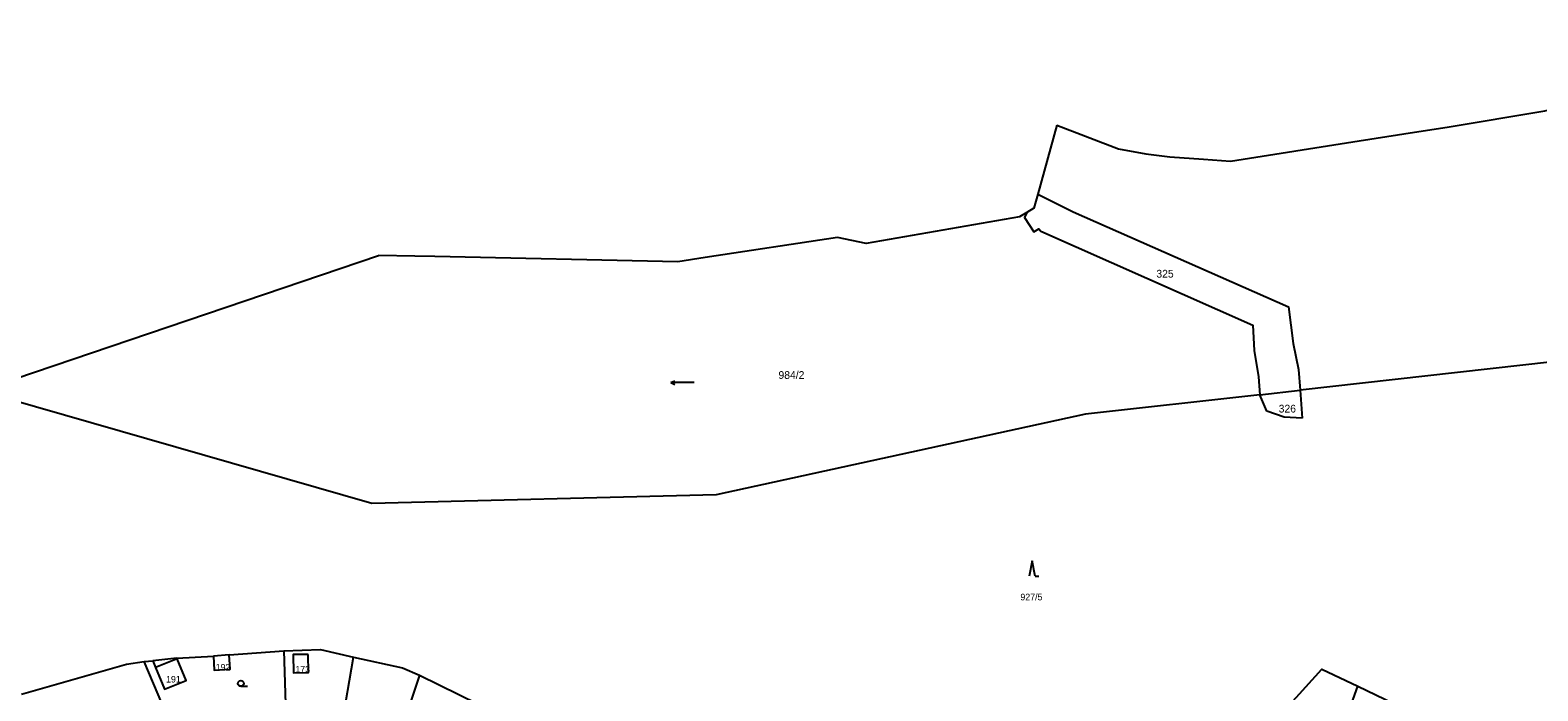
# Model space of a CAD drawing. Extents: x -7476540 to -746055, y -11317203 to -1129777.
# Drawn here: x -751034.6 to -750645.6, y -1130897.4 to -1130726.9 of the extents above; entities that cross this region are included whole.
import ezdxf

# ---------------------------------------------------------------- set-up
doc = ezdxf.new("R2010")
doc.units = 0
for name, color, linetype in [('Hranice parcel', 7, 'Continuous'), ('Parcelní čísla', 7, 'Continuous'), ('Vnitřní kresba', 7, 'Continuous'), ('Značky kultur', 7, 'Continuous')]:
    doc.layers.add(name, color=color, linetype=linetype)

msp = doc.modelspace()

# ---------------------------------------------------------------- linework, layer by layer
at = {"layer": 'Hranice parcel'}
for p, q in [((-750769.73, -1130751.39), (-750774.64, -1130769.17)), ((-750769.73, -1130751.39), (-750753.78, -1130757.5)), ((-750691.69, -1130755.42), (-750677.41, -1130753.17)), ((-750753.78, -1130757.5), (-750746.76, -1130758.8)), ((-750724.95, -1130760.65), (-750691.69, -1130755.42)), ((-750746.76, -1130758.8), (-750740.6, -1130759.58)), ((-750740.6, -1130759.58), (-750731.88, -1130760.18)), ((-750731.88, -1130760.18), (-750724.95, -1130760.65)), ((-751047.71, -1130819.99), (-750944.73, -1130785.05)), ((-750935.4, -1130785.22), (-750944.73, -1130785.05)), ((-750707.41, -1130814.44), (-750706.94, -1130819.8)), ((-750717.71, -1130816.39), (-750717.32, -1130820.97)), ((-750717.32, -1130820.97), (-750706.94, -1130819.8)), ((-750706.94, -1130819.8), (-750706.41, -1130827.05)), ((-750715.58, -1130825.26), (-750717.32, -1130820.97)), ((-751005.24, -1130889.84), (-751002.97, -1130889.66)), ((-750985.26, -1130936.86), (-751005.24, -1130889.84)), ((-750996.78, -1130889.01), (-751002.97, -1130889.66)), ((-750996.78, -1130889.01), (-750987.33, -1130888.49)), ((-750983.28, -1130888.15), (-750987.33, -1130888.49)), ((-750983.28, -1130888.15), (-750969.18, -1130887.14)), ((-750969.18, -1130887.14), (-750968.63, -1130903.54)), ((-750958.66, -1130932.52), (-750951.18, -1130888.7)), ((-750934.14, -1130893.34), (-750947.69, -1130934.14)), ((-750706.94, -1130937.58), (-750692.03, -1130896.19))]:
    msp.add_line(p, q, dxfattribs=at)
for points in [[(-750677.41, -1130753.17), (-750669.01, -1130751.86), (-750643.79, -1130747.71), (-750620.98, -1130742.49), (-750585.9, -1130733.64), (-750562.47, -1130726.85)], [(-750774.64, -1130769.17), (-750775.66, -1130772.85), (-750777.43, -1130773.93)], [(-750774.64, -1130769.17), (-750765.52, -1130773.73), (-750709.93, -1130798.25), (-750708.79, -1130807.78), (-750707.41, -1130814.44)], [(-750777.43, -1130773.93), (-750779.33, -1130775.08), (-750818.95, -1130781.97), (-750826.36, -1130780.41), (-750860.46, -1130785.57)], [(-750777.43, -1130773.93), (-750778.09, -1130775.26), (-750775.67, -1130778.96), (-750774.37, -1130778.15), (-750773.88, -1130778.73), (-750719.15, -1130802.98), (-750718.79, -1130809.52), (-750717.71, -1130816.39)], [(-750542.51, -1130784.25), (-750595.13, -1130799), (-750641.84, -1130812.5), (-750706.94, -1130819.8)], [(-750860.46, -1130785.57), (-750867.48, -1130786.64), (-750930.18, -1130785.31), (-750935.4, -1130785.22)], [(-750717.32, -1130820.97), (-750762.34, -1130826.02), (-750857.66, -1130846.85), (-750946.44, -1130849.03), (-751047.71, -1130819.99)], [(-750706.41, -1130827.05), (-750711.1, -1130826.75), (-750715.58, -1130825.26)], [(-751036.87, -1130898.28), (-751009.76, -1130890.51), (-751005.24, -1130889.84)], [(-751002.97, -1130889.66), (-751002.26, -1130891.41), (-750999.99, -1130896.99), (-750994.41, -1130894.74), (-750996.72, -1130889.16), (-750996.78, -1130889.01)], [(-750987.33, -1130888.49), (-750987.12, -1130892.12), (-750982.98, -1130891.86), (-750983.28, -1130888.15)], [(-750969.18, -1130887.14), (-750959.71, -1130886.74), (-750951.18, -1130888.7)], [(-750962.9, -1130888.02), (-750966.75, -1130888.08), (-750966.71, -1130892.8), (-750962.79, -1130892.71), (-750962.9, -1130888.02)], [(-750951.18, -1130888.7), (-750938.58, -1130891.47), (-750934.14, -1130893.34)], [(-750934.14, -1130893.34), (-750908.78, -1130905.87), (-750904.82, -1130906.58)], [(-750761.64, -1130926.26), (-750736.55, -1130924.13), (-750724.71, -1130916.65), (-750719.47, -1130911.9), (-750701.35, -1130891.83), (-750692.03, -1130896.19)], [(-750692.03, -1130896.19), (-750673.46, -1130905.17), (-750670.18, -1130909.99)]]:
    msp.add_lwpolyline(points, dxfattribs=at)
at = {"layer": 'Vnitřní kresba'}
msp.add_line((-750996.72, -1130889.16), (-751002.26, -1130891.41), dxfattribs=at)
at = {"layer": 'Značky kultur'}
for p, q in [((-750869.31, -1130817.85), (-750868.33, -1130817.35)), ((-750863.31, -1130817.85), (-750869.31, -1130817.85)), ((-750869.31, -1130817.85), (-750868.33, -1130818.35)), ((-750776.11, -1130863.85), (-750776.86, -1130867.85)), ((-750775.36, -1130867.85), (-750776.11, -1130863.85)), ((-750775.36, -1130867.85), (-750774.36, -1130867.85)), ((-750980.28, -1130896.26), (-750978.53, -1130896.26))]:
    msp.add_line(p, q, dxfattribs=at)
msp.add_circle((-750980.28, -1130895.51), 0.75, dxfattribs=at)

# ---------------------------------------------------------------- texts
at = {"layer": 'Parcelní čísla'}
for s, height, p in [('325', 2, (-750744.05, -1130790.74)), ('984/2', 2, (-750841.55, -1130816.89)), ('326', 2, (-750712.49, -1130825.57)), ('927/5', 1.7, (-750779.13, -1130874.05)), ('191', 1.7, (-750999.56, -1130895.28)), ('192', 1.7, (-750986.76, -1130892.18)), ('173', 1.7, (-750966.19, -1130892.7))]:
    msp.add_text(s, height=height, dxfattribs=at).set_placement(p)

doc.saveas('drawing.dxf')
